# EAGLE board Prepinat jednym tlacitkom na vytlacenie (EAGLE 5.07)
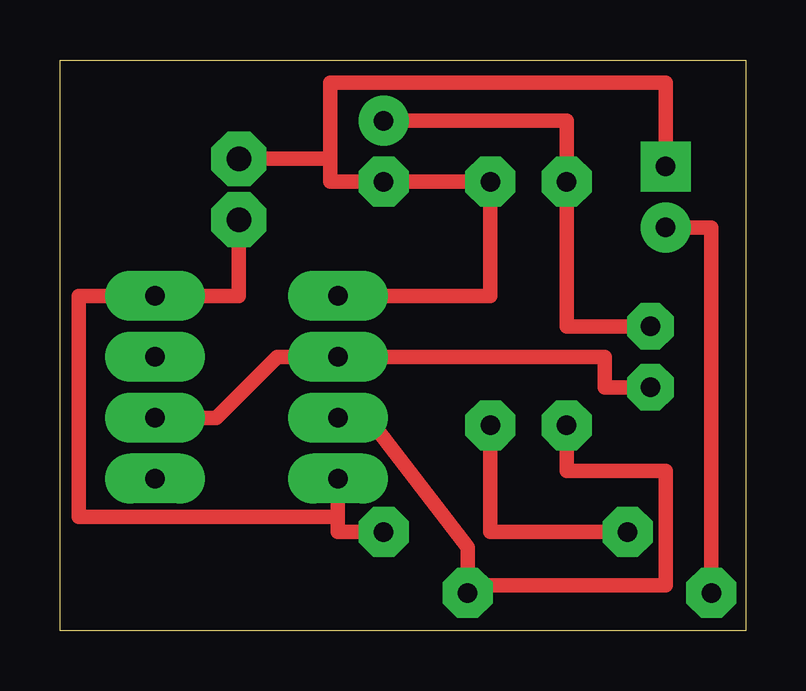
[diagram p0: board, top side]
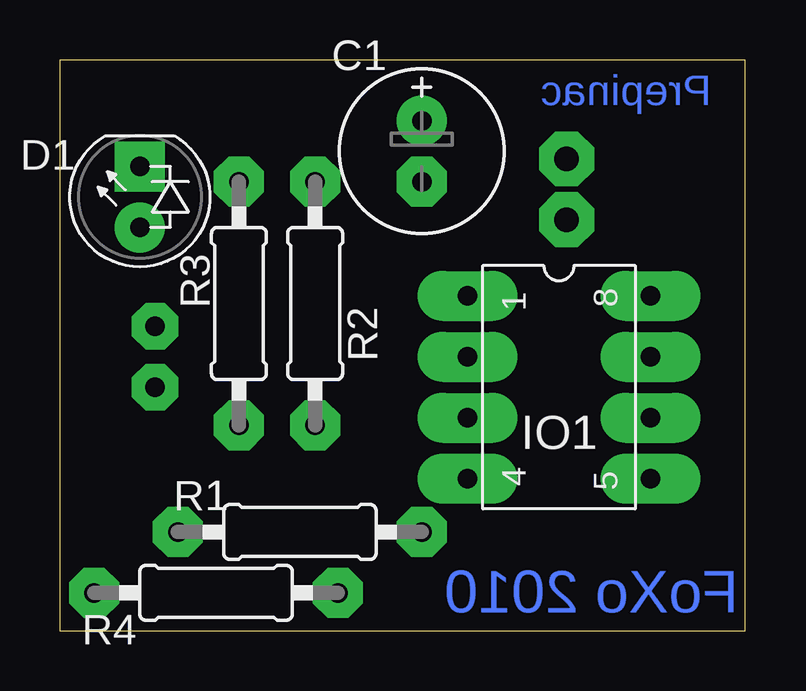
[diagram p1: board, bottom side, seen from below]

Size 28.56 x 23.8 mm. Coordinates in mm from the lower left corner, seen from the top.
Outline: 28.56,0 0,0 0,23.8 28.56,23.8 28.56,0
Copper layers (1*16): Top 0.035mm / dielectric 1.5mm / Bottom 0.035mm
Design rules "default *": minimum track width 10mil, minimum drill 24mil, track to track 8mil, track to pad 8mil, pad to pad 8mil, via to via 8mil, smd to smd 8mil, copper to edge 40mil, drill to drill 8mil, minimum pad ring 25mil, minimum via ring 8mil, stop-mask expansion 4mil, vias tented up to drill 0mil, thermal gap 10mil

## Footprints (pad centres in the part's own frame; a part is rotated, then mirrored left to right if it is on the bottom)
E2,5-7 = drill 0.813 pad 1.6 round: + -1.27,0 | drill 0.813 pad 1.6 octagon: - 1.27,0
LED_5 = drill 0.813 pad 1.778 round: A -1.27,0 | drill 0.813 pad 1.778 square: K 1.27,0
DIL8 = drill 0.813 pad 1.4 long: 1 -3.81,-3.81; 2 -1.27,-3.81; 3 1.27,-3.81; 4 3.81,-3.81; 5 3.81,3.81; 6 1.27,3.81; 7 -1.27,3.81; 8 -3.81,3.81
PAD_1 = drill 1.016 pad 2.184 octagon: 1 0,0
0207/10 = drill 0.813 octagon: 1 -5.08,0; 2 5.08,0

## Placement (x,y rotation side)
C1  1uF  [E2,5-7]  13.49,20 270 bottom
D1  LED_5  [LED_5]  25.23,18.09 90 bottom
IO1  555  [DIL8]  7.77,10.15 270 bottom
PAD1  + 12 V  [PAD_1]  7.46,17.14 90 bottom
PAD2  0V  [PAD_1]  7.46,19.68 90 bottom
R1  10K  [0207/10]  18.57,4.12 0 bottom
R2  10K  [0207/10]  17.93,13.65 90 bottom
R3  100K  [0207/10]  21.11,13.65 90 bottom
R4  470R  [0207/10]  22.06,1.58 180 bottom

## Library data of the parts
C1 R1-R4 = rcl
D1 IO1 PAD1 PAD2 = #PaJa_20

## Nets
N$1: IO1.2 IO1.6
N$2: C1.+
N$3: IO1.3 R3.1
N$4: C1.- D1.K IO1.1 R2.2
N$6: IO1.4
S$1: IO1.8
S$4: D1.A R4.2
S$6: R1.1

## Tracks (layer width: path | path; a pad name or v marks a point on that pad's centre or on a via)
N$1
  Top 0.61: IO1.6 6.5,8.88 9.04,11.43 IO1.2 22.7,11.43 22.7,10.15 23.65,10.15
N$2
  Top 0.61: C1.+ 21.11,21.27 21.11,12.7 23.65,12.7
N$3
  Top 0.61: 12.85,8.88 16.98,3.49 16.98,1.9 25.24,1.9 25.24,6.66 21.11,6.66 R3.1
  Top 0.813: 12.85,8.88 IO1.3
N$4
  Top 0.61: IO1.1 17.93,13.96 R2.2 C1.- 11.27,18.73 11.27,19.68 | 11.27,19.68 11.27,22.86 25.24,22.86 D1.K | 11.27,19.68 8.41,19.68
N$6
  Top 0.61: 11.58,4.76 IO1.4 | 11.58,4.76 0.79,4.76 | 12.85,4.12 11.58,4.12 11.58,4.76
S$1
  Top 0.61: IO1.8 0.79,13.96 0.79,4.76
S$2  (via drill 0.81 pad 1.93)
  other vias: 24.6,12.7
S$3  (via drill 0.81 pad 1.93)
  other vias: 24.6,10.15
S$4
  Top 0.61: R4.2 27.14,16.82 D1.A
S$5
  Top 0.61: 4.28,13.96 7.45,13.96 7.45,16.19
S$6
  Top 0.61: 17.93,8.57 17.93,4.12 R1.1

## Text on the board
Bottom: Prepinac | FoXo 2010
